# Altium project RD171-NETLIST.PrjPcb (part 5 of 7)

## Sheet 6.SchDoc
size 420 x 297 mm
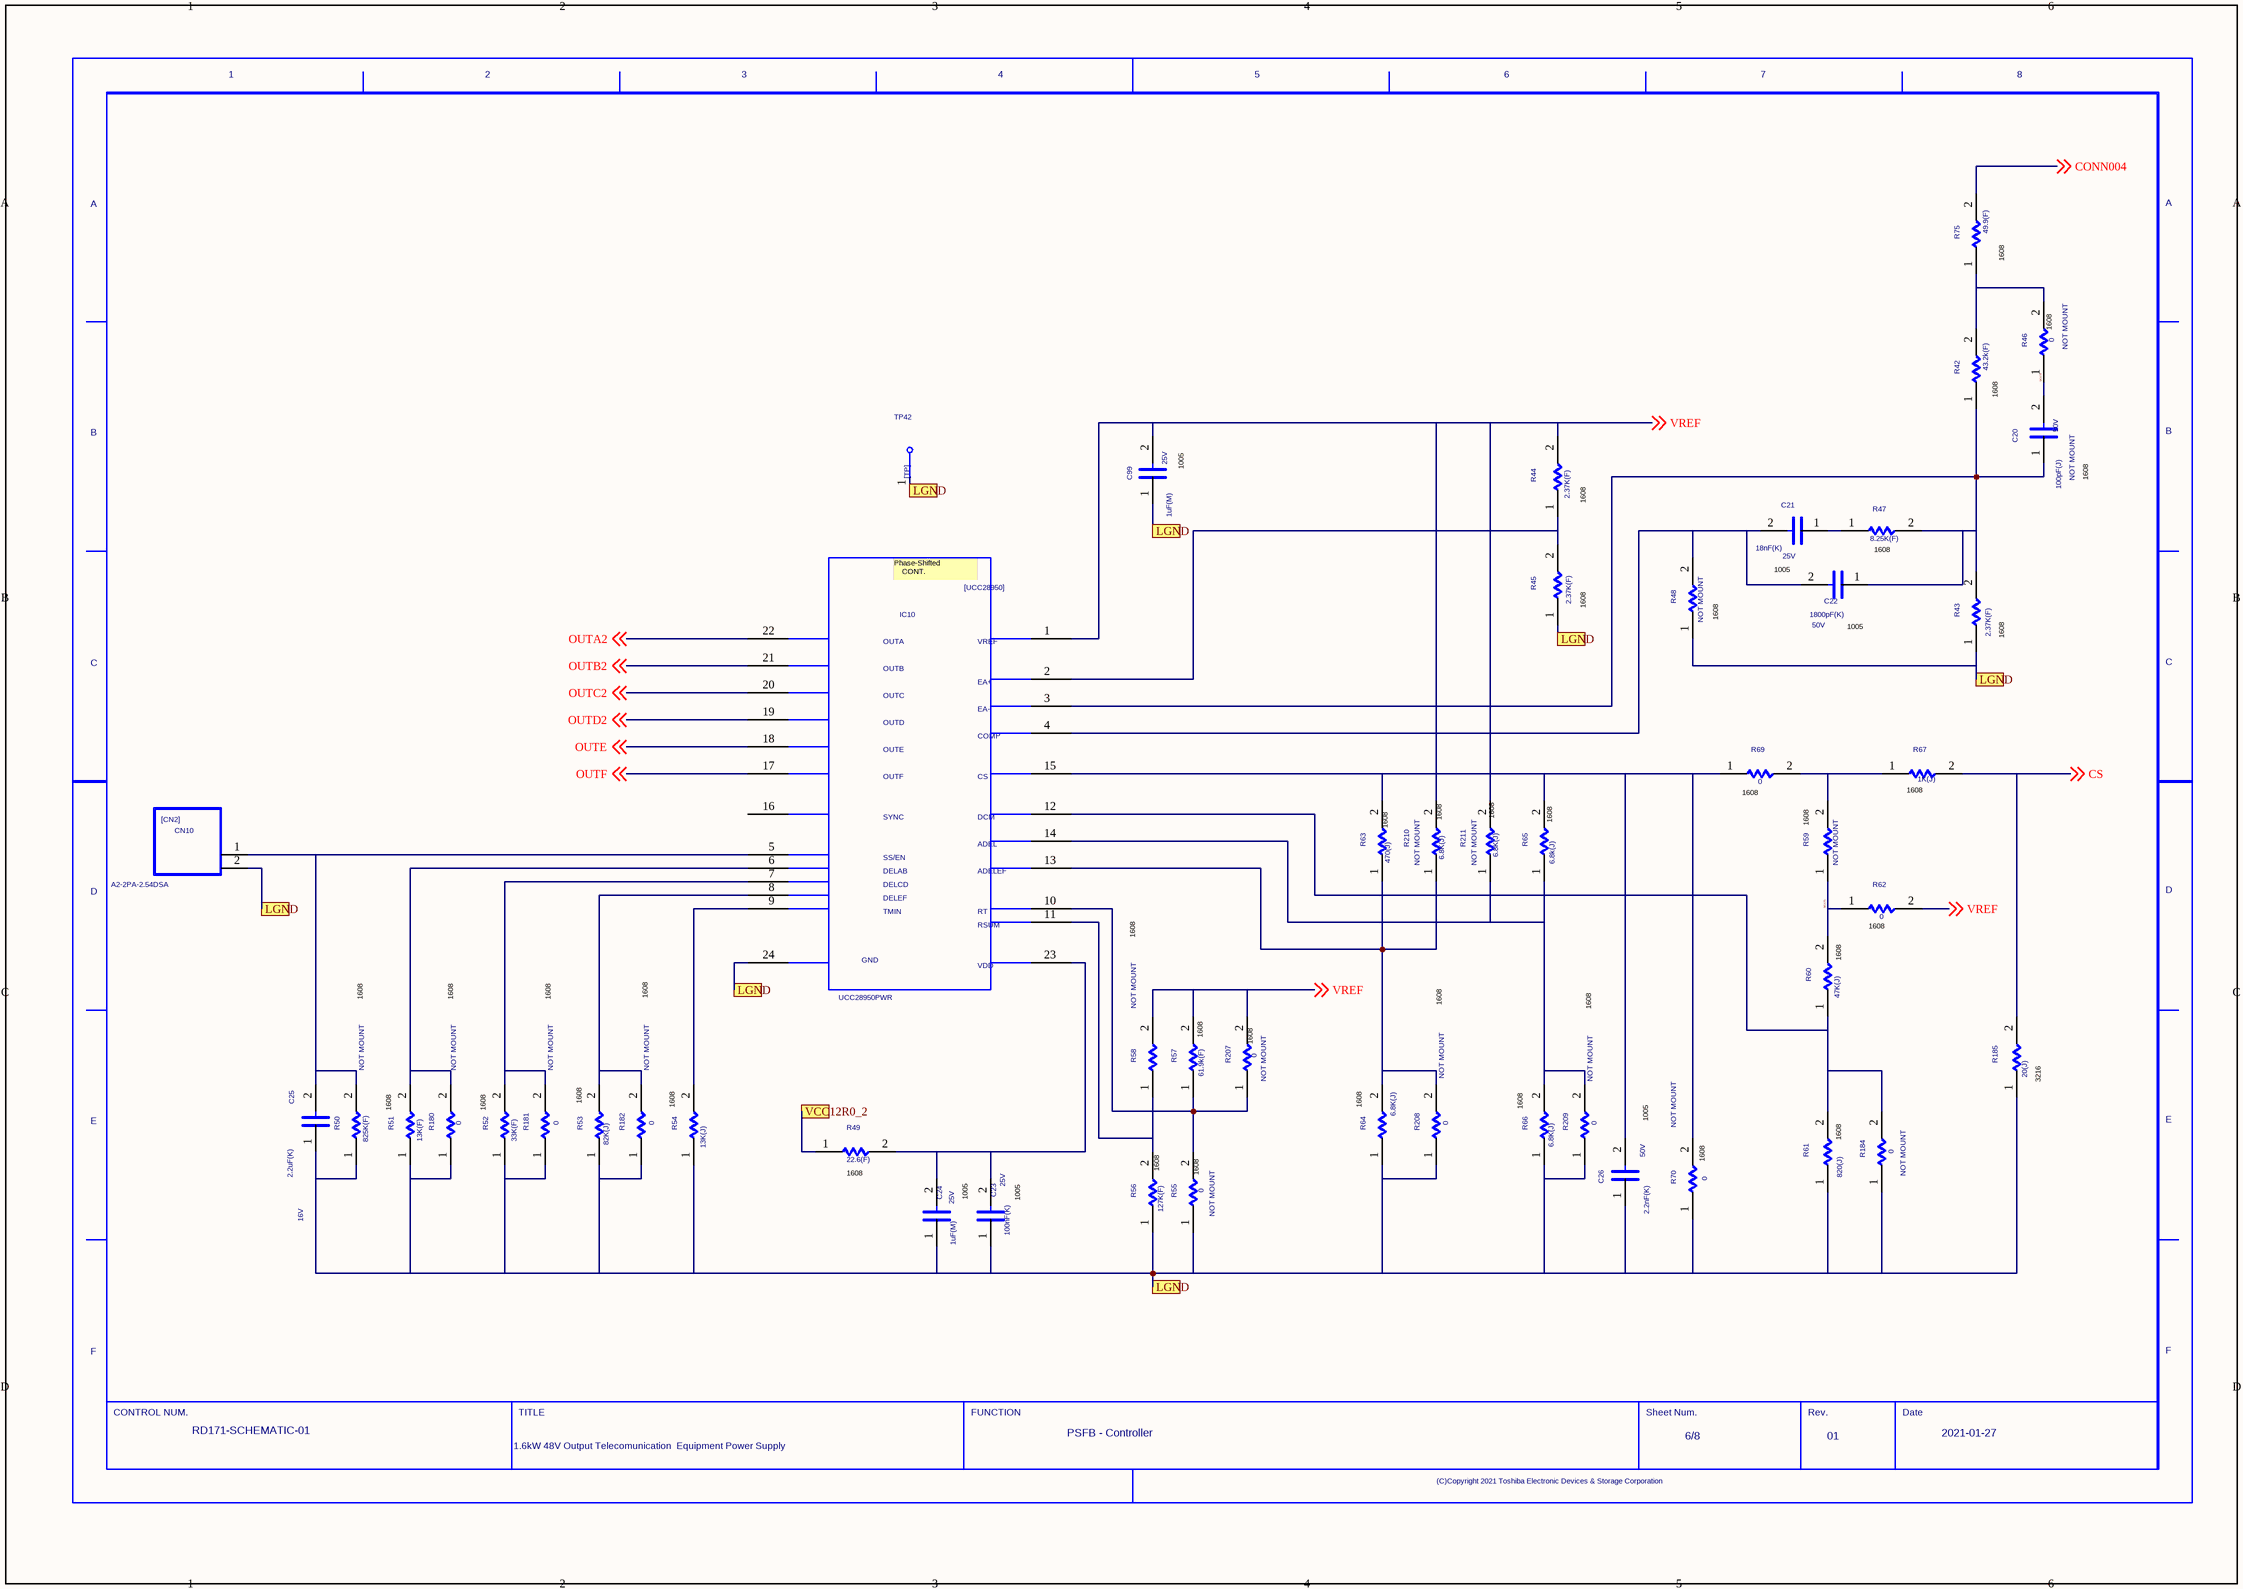
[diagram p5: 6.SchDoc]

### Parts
(Parts that share a designator on the sheet are numbered #1, #2 ... from top to bottom, then left to right.)
C20  VAL2: 50V  VAL1: 100pF(J)  NOTMOUNT: NOT MOUNT  (hidden comment: 100pF)
C21  VAL2: 25V  VAL1: 18nF(K)  (hidden comment: 18nF)
C22  VAL2: 50V  VAL1: 1800pF(K)  (hidden comment: 1800pF)
C23  VAL2: 25V  VAL1: 100nF(K)  (hidden comment: 100nF)
C24  VAL2: 25V  VAL1: 1uF(M)  (hidden comment: 1uF)
C25  VAL2: 16V  VAL1: 2.2uF(K)  (hidden comment: 2.2uF)
C26  VAL2: 50V  VAL1: 2.2nF(K)  (hidden comment: 2.2nF)
C99  VAL2: 25V  VAL1: 1uF(M)  (hidden comment: 1uF)
CN10  CN10  [A2-2PA-2.54DSA]  (value not drawn)
IC10  IC10  [UCC28950PWR]  (value not drawn)
R42  VAL1: 43.2k(F)  [RN73H1JTTD4322F25]  (hidden comment: 43.2k)
R43  VAL1: 2.37K(F)  (hidden comment: 2.37k)
R44  VAL1: 2.37K(F)  (hidden comment: 2.37k)
R45  VAL1: 2.37K(F)  (hidden comment: 2.37k)
R46  NOTMOUNT: NOT MOUNT  (hidden comment: 0)
R47  VAL1: 8.25K(F)  (hidden comment: 8.25k)
R48  NOTMOUNT: NOT MOUNT  (hidden comment: 0)
R49  VAL1: 22.6(F)  (hidden comment: 22.6)
R50  VAL1: 825K(F)  NOTMOUNT: NOT MOUNT  (hidden comment: 825k)
R51  VAL1: 13K(F)  (hidden comment: 13k)
R52  VAL1: 33K(F)  (hidden comment: 33k)
R53  VAL1: 82K(J)  (hidden comment: 100k)
R54  VAL1: 13K(J)  (hidden comment: 13k)
R55  NOTMOUNT: NOT MOUNT  (hidden comment: 0)
R56  VAL1: 127K(F)  (hidden comment: 127k)
R57  VAL1: 61.9k(F)  [RN73H1JTTD6192F50]  (hidden comment: 61.9k)
R58  NOTMOUNT: NOT MOUNT  (hidden comment: 0)
R59  NOTMOUNT: NOT MOUNT  (hidden comment: 0)
R60  VAL1: 47K(J)  (hidden comment: 47k)
R61  VAL1: 820(J)  (hidden comment: 820)
R62  0
R63  VAL1: 470(J)  (hidden comment: 100)
R64  VAL1: 6.8K(J)  (hidden comment: 6.8k)
R65  VAL1: 6.8k(J)  (hidden comment: 6.8k)
R66  VAL1: 6.8K(J)  (hidden comment: 6.8k)
R67  VAL1: 1K(J)  (hidden comment: 1K)
R69  0
R70  NOTMOUNT: NOT MOUNT  (hidden comment: 0)
R75  VAL1: 49.9(F)  (hidden comment: 49.9)
R180  NOTMOUNT: NOT MOUNT  (hidden comment: 0)
R181  NOTMOUNT: NOT MOUNT  (hidden comment: 0)
R182  NOTMOUNT: NOT MOUNT  (hidden comment: 0)
R184  NOTMOUNT: NOT MOUNT  (hidden comment: 0)
R185  VAL1: 20(J)  (hidden comment: 20)
R207  NOTMOUNT: NOT MOUNT  (hidden comment: 0)
R208  NOTMOUNT: NOT MOUNT  (hidden comment: 0)
R209  NOTMOUNT: NOT MOUNT  (hidden comment: 0)
R210  NOTMOUNT: NOT MOUNT  VAL1: 6.8K(J)  (hidden comment: 6.8k)
R211  NOTMOUNT: NOT MOUNT  VAL1: 6.8K(J)  (hidden comment: 6.8k)
TP42  TP42  [LC-22-S-BLACK]  (value not drawn)
U?#6  DATE: 2021-01-27  REVISION: 01  SHEETNUMBER: 6/8  FUNCTION: PSFB - Controller  TITLE: 1.6kW 48V Output Telecomunication / Equipment Power Supply  DRAWINGNUMBER: RD171-SCHEMATIC-01  (hidden comment: WAKU_DEF100)

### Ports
LGND, VCC12R0_2

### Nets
CONN004: R75.2 ; off-sheet CONN004
CS: R67.2 R185.2 ; off-sheet CS
LGND: C23.1 C24.1 C25.1 C26.1 C99.1 CN10.2 IC10.24 R43.1 R45.1 R48.1 R50.1 R51.1 R52.1 R53.1 R54.1 R55.1 R56.1 R61.1 R64.1 R66.1 R70.1 R180.1 R181.1 R182.1 R184.1 R185.1 R208.1 R209.1 TP42.1 ; port LGND
OUTA2: IC10.22 ; off-sheet OUTA2
OUTB2: IC10.21 ; off-sheet OUTB2
OUTC2: IC10.20 ; off-sheet OUTC2
OUTD2: IC10.19 ; off-sheet OUTD2
OUTE: IC10.18 ; off-sheet OUTE
OUTF: IC10.17 ; off-sheet OUTF
SIG148: IC10.6 R51.2 R180.2
SIG149: IC10.7 R52.2 R181.2
SIG150: IC10.8 R53.2 R182.2
SIG151: IC10.9 R54.2
SIG152: C25.2 CN10.1 IC10.5 R50.2
SIG154: IC10.2 R44.1 R45.2
SIG156: C20.1 C22.1 IC10.3 R42.1 R43.2 R47.2
SIG157: R42.2 R46.2 R75.1
SIG167: C21.1 R47.1
SIG168: C21.2 C22.2 IC10.4 R48.2
SIG170: C20.2 R46.1
SIG171: IC10.14 R65.1 R66.2 R209.2 R211.1
SIG172: IC10.13 R63.1 R64.2 R208.2 R210.1
SIG173: C26.2 IC10.15 R63.2 R65.2 R69.1 R70.2
SIG174: R59.2 R67.1 R69.2
SIG175: R59.1 R60.2 R62.1
SIG177: IC10.12 R60.1 R61.2 R184.2
SIG179: IC10.10 R55.2 R57.1 R207.1
SIG181: IC10.11 R56.2 R58.1
SIG183: C23.2 C24.2 IC10.23 R49.2
VREF: C99.2 IC10.1 R44.2 R57.2 R58.2 R62.2 R207.2 R210.2 R211.2 ; off-sheet VREF
NetC809_2: R49.1 ; port VCC12R0_2

Not connected (* = marked no-connect by the designer): IC10 16

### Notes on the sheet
- (near R75) 1608
- (near R46) 1608
- (near R42) 1608
- (near C99) 1005
- (near R44) 1608
- (near C20) 1608
- 1005
- (near R47) 1608
- (near R45) 1608
- (near R48) 1608
- (near C22) 1005
- (near R43) 1608
- (near R69) 1608
- (near R67) 1608
- (near R63) 1608
- (near R210) 1608
- (near R211) 1608
- (near R65) 1608
- (near R59) 1608
- 1608
- (near R62) 1608
- (near R60) 1608
- (near R57) 1608
- (near R207) 1608
- (near R51) 1608
- (near R52) 1608
- (near R53) 1608
- (near R64) 1608
- (near R66) 1608
- (near R61) 1608
- (near R185) 3216
- (near R49) 1608
- (near C23) 1005
- (near R56) 1608
- (near R55) 1608
- (near R70) 1608

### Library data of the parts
C20 = C: PARTNAME: Chip1608_GS_1; ORIGINALSYMBOLORIGIN: (0,0); TIME: 16:40:04; UPDATEUSER: t5459927; SAVECOUNT: 1; QUADMODEL: CON_100N; FUNCTION: C_C.Normal_package; NOMINALCAPACITA: 100n; RATEDVOLTAGE: 25; CDMASTERCADCELG: KC0008; TEMPCHARACTERI2: B; SIZECODESMD: 1608; OUMEMAKER: MRT 村田製作所; COMP: PRT_48; ADSMODELNAME: s_GRM188B11E104KA01D; PMPRODUCTSTYPEG: PC1; FNLEADFREETHET1GT2GMCTH1: 3_1_N; VAL3: GRM1885C1H101JA01D; CAPACITANCETOLE: K; OUMECLASSIFICATION: セラミックコンデンサ; OUMEMAKERKATAMEI: GRM188B11E104KA01D; INSTANCENAME: INS8954
C21 = C: PARTNAME: Chip1005_GS_2; ORIGINALSYMBOLORIGIN: (0,0); TIME: 16:40:04; UPDATEUSER: t5459927; SAVECOUNT: 1; QUADMODEL: CON_5.6N; FUNCTION: C_C.Normal_package; NOMINALCAPACITA: 5.6n; RATEDVOLTAGE: 25; CDMASTERCADCELG: KC0005; MAKER: MURATA; TEMPCHARACTERI2: B; SIZECODESMD: 1005; OUMEMAKER: MRT 村田製作所; ADSCNVFLAG: ON; ADSCOMPONENTNAME: C_1005; COMP: PRT_52; ADSMODELNAME: s_GRM155B11E562KA01D; PMPRODUCTSTYPEG: HD1; FNLEADFREETHET1GT2GMCTH1: 2_0_N; VAL3: GRM155R71E183KA61D; CAPACITANCETOLE: K; OUMECLASSIFICATION: セラミックコンデンサ; OUMEMAKERKATAMEI: GRM155B11E562KA01D; INSTANCENAME: INS8656
C22 = C: PARTNAME: Chip1005_GS_2; ORIGINALSYMBOLORIGIN: (0,0); TIME: 16:40:04; UPDATEUSER: t5459927; SAVECOUNT: 1; QUADMODEL: CON_560P; FUNCTION: C_C.Normal_package; NOMINALCAPACITA: 560p; RATEDVOLTAGE: 50; CDMASTERCADCELG: KC0005; MAKER: MURATA; TEMPCHARACTERI2: B; SIZECODESMD: 1005; OUMEMAKER: TDK ＴＤＫ; ADSCNVFLAG: ON; ADSCOMPONENTNAME: C_1005; COMP: PRT_52; ADSMODELNAME: s_C1005JB1H561KT; PMPRODUCTSTYPEG: HD1-PC1; FNLEADFREETHET1GT2GMCTH1: 2_0_N; VAL3: GRM155R71H182KA01D; CAPACITANCETOLE: K; OUMECLASSIFICATION: セラミックコンデンサ; OUMEMAKERKATAMEI: C1005JB1H561KT; INSTANCENAME: INS8666
C23 = C: PARTNAME: Chip1005_GS_2; ORIGINALSYMBOLORIGIN: (0,0); TIME: 16:40:04; UPDATEUSER: t5459927; SAVECOUNT: 1; QUADMODEL: CON_100N; FUNCTION: C_C.Normal_package; NOMINALCAPACITA: 100n; RATEDVOLTAGE: 25; CDMASTERCADCELG: KC0005; MAKER: TDK; SIZECODESMD: 1005; OUMEMAKER: MRT 村田製作所; COMP: PRT_52; ADSMODELNAME: s_GRM155R71E104KE14D; FNLEADFREETHET1GT2GMCTH1: N_N_N; VAL3: C1005X7R1E104K050BB; CAPACITANCETOLE: K; OUMECLASSIFICATION: セラミックコンデンサ; OUMEMAKERKATAMEI: GRM155R71E104KE14D; INSTANCENAME: INS8708
C24 = C: PARTNAME: Chip1005_GS_2; ORIGINALSYMBOLORIGIN: (0,0); TIME: 16:40:04; UPDATEUSER: t5459927; SAVECOUNT: 1; QUADMODEL: CON_1U; FUNCTION: C_C.Normal_package; NOMINALCAPACITA: 1u; RATEDVOLTAGE: 25; CDMASTERCADCELG: KC0005; MAKER: TDK; TEMPCHARACTERI2: B; SIZECODESMD: 1005; OUMEMAKER: MRT 村田製作所; COMP: PRT_52; ADSMODELNAME: s_GRM155B31E105KA12D; PMPRODUCTSTYPEG: HD1; FNLEADFREETHET1GT2GMCTH1: 3_0_N; VAL3: C1005X5R1E105M050BC; CAPACITANCETOLE: K; OUMECLASSIFICATION: セラミックコンデンサ; OUMEMAKERKATAMEI: GRM155B31E105KA12D; INSTANCENAME: INS8718
C25 = C: PARTNAME: Chip1005_GS_2; ORIGINALSYMBOLORIGIN: (0,0); TIME: 16:40:04; UPDATEUSER: t5459927; SAVECOUNT: 1; FUNCTION: C_C.Normal_package; NOMINALCAPACITA: 150n; RATEDVOLTAGE: 25; CDMASTERCADCELG: KC0005; MAKER: MURATA; SIZECODESMD: 1005; COMP: PRT_52; ADSMODELNAME: s_GRM155C81C225KE11; PMPRODUCTSTYPEG: HD1; FNLEADFREETHET1GT2GMCTH1: 3_0_N; VAL3: GRM155C81C225KE11; CAPACITANCETOLE: K; OUMECLASSIFICATION: セラミックコンデンサ; INSTANCENAME: INS8624
C26 = C: PARTNAME: Chip1005_GS_2; ORIGINALSYMBOLORIGIN: (0,0); TIME: 16:40:04; UPDATEUSER: t5459927; SAVECOUNT: 1; QUADMODEL: CON_2.2N; FUNCTION: C_C.Normal_package; NOMINALCAPACITA: 2.2n; RATEDVOLTAGE: 50; CDMASTERCADCELG: KC0005; MAKER: TDK; TEMPCHARACTERI2: B; SIZECODESMD: 1005; OUMEMAKER: TYD 太陽誘電; COMP: PRT_52; ADSMODELNAME: s_UMK105BJ222KV_F; PMPRODUCTSTYPEG: HD1-PC1; FNLEADFREETHET1GT2GMCTH1: 2_0_N; VAL3: UMK105BJ222KV-F; CAPACITANCETOLE: K; OUMECLASSIFICATION: セラミックコンデンサ; INSTANCENAME: INS8762
C99 = C: PARTNAME: Chip1005_GS_2; ORIGINALSYMBOLORIGIN: (0,0); TIME: 16:40:04; UPDATEUSER: t5459927; SAVECOUNT: 1; QUADMODEL: CON_1U; FUNCTION: C_C.Normal_package; NOMINALCAPACITA: 1u; RATEDVOLTAGE: 25; CDMASTERCADCELG: KC0005; MAKER: TDK; TEMPCHARACTERI2: B; SIZECODESMD: 1005; OUMEMAKER: MRT 村田製作所; COMP: PRT_52; ADSMODELNAME: s_GRM155B31E105KA12D; PMPRODUCTSTYPEG: HD1; FNLEADFREETHET1GT2GMCTH1: 3_0_N; VAL3: C1005X5R1E105M050BC; CAPACITANCETOLE: K; OUMECLASSIFICATION: セラミックコンデンサ; OUMEMAKERKATAMEI: GRM155B31E105KA12D; INSTANCENAME: INS8728
CN10 = CN2: PARTNAME: A2-2PA-2.54DSA_HR; ORIGINALSYMBOLORIGIN: (0,0); TIME: 16:40:05; UPDATEUSER: t5459927; SAVECOUNT: 1; COMP: PRT_56; FUNCTION: CN2_CN2.Normal_package; MAKER: HIROSE; INSTANCENAME: INS9156
IC10 = L28950: PARTNAME: UCC28950PWR_GS_1; UPDATEUSER: t5459927; UPDATETIME: 16:40:04; SAVECOUNT: 1; SAVEAREA0: -41645,-82886,84834,-24583; ORIGINALSYMBOLORIGIN: (0,0); COMP: PRT_16; FUNCTION: L28950_L28950.Normal_package; MAKER: TEXAS; INSTANCENAME: INS8570
R42 = R: PARTNAME: Chip1608_GS_1; ORIGINALSYMBOLORIGIN: (0,0); TIME: 16:40:04; UPDATEUSER: t5459927; SAVECOUNT: 1; QUADMODEL: RES_9.09K; FUNCTION: R_R.Normal_package; CDMASTERCADCELG: KC0008; MAKER: PANASONIC; RESISTANCETOLER: B; SIZECODESMD: 1608; OUMEMAKER: KOA コーア; POWERRATING: 100m; MOUNTINGFORMSMD: SMD; NOMINALRESISTAN: 9.09K; COMP: PRT_8; ADSMODELNAME: s_RN73H1JTTD4322F25; PMPRODUCTSTYPEG: DME; FNLEADFREETHET1GT2GMCTH1: N_N_N; VAL3: ERJ-3EKF9091V; VAL2: 100mW,±1%; OUMECLASSIFICATION: 表面実装用固定抵抗器; OUMEMAKERKATAMEI: RN73H1JTTD9091B10; INSTANCENAME: INS8646
R43 = R: PARTNAME: Chip1608_GS_1; ORIGINALSYMBOLORIGIN: (0,0); TIME: 16:40:04; UPDATEUSER: t5459927; SAVECOUNT: 1; QUADMODEL: RES_2.2K; FUNCTION: R_R.Normal_package; CDMASTERCADCELG: KC0165; MAKER: PANASONIC; RESISTANCETOLER: F; SIZECODESMD: 1608; OUMEMAKER: NAE パナソニックエレクトロニックデバイス; POWERRATING: 100m; MOUNTINGFORMSMD: SMD; NOMINALRESISTAN: 2.2K; COMP: PRT_8; ADSMODELNAME: s_ERJ3EKF2201V@@; PMPRODUCTSTYPEG: DA; FNLEADFREETHET1GT2GMCTH1: 3_2_N; VAL3: ERJ-3EKF2371V; VAL2: 100mW,±1%; OUMECLASSIFICATION: 表面実装用固定抵抗器; OUMEMAKERKATAMEI: ERJ3EKF2201V@@; INSTANCENAME: INS8966
R44 = R: PARTNAME: Chip1608_GS_1; ORIGINALSYMBOLORIGIN: (0,0); TIME: 16:40:04; UPDATEUSER: t5459927; SAVECOUNT: 1; QUADMODEL: RES_2.2K; FUNCTION: R_R.Normal_package; CDMASTERCADCELG: KC0165; MAKER: PANASONIC; RESISTANCETOLER: F; SIZECODESMD: 1608; OUMEMAKER: NAE パナソニックエレクトロニックデバイス; POWERRATING: 100m; MOUNTINGFORMSMD: SMD; NOMINALRESISTAN: 2.2K; COMP: PRT_8; ADSMODELNAME: s_ERJ3EKF2201V@@; PMPRODUCTSTYPEG: DA; FNLEADFREETHET1GT2GMCTH1: 3_2_N; VAL3: ERJ-3EKF2371V; VAL2: 100mW,±1%; OUMECLASSIFICATION: 表面実装用固定抵抗器; OUMEMAKERKATAMEI: ERJ3EKF2201V@@; INSTANCENAME: INS8878
R45 = R: PARTNAME: Chip1608_GS_1; ORIGINALSYMBOLORIGIN: (0,0); TIME: 16:40:04; UPDATEUSER: t5459927; SAVECOUNT: 1; QUADMODEL: RES_2.2K; FUNCTION: R_R.Normal_package; CDMASTERCADCELG: KC0165; MAKER: PANASONIC; RESISTANCETOLER: F; SIZECODESMD: 1608; OUMEMAKER: NAE パナソニックエレクトロニックデバイス; POWERRATING: 100m; MOUNTINGFORMSMD: SMD; NOMINALRESISTAN: 2.2K; COMP: PRT_8; ADSMODELNAME: s_ERJ3EKF2201V@@; PMPRODUCTSTYPEG: DA; FNLEADFREETHET1GT2GMCTH1: 3_2_N; VAL3: ERJ-3EKF2371V; VAL2: 100mW,±1%; OUMECLASSIFICATION: 表面実装用固定抵抗器; OUMEMAKERKATAMEI: ERJ3EKF2201V@@; INSTANCENAME: INS8868
R46 = R: PARTNAME: Chip1608_GS_1; ORIGINALSYMBOLORIGIN: (0,0); TIME: 16:40:04; UPDATEUSER: t5459927; SAVECOUNT: 1; QUADMODEL: RES_9.09K; FUNCTION: R_R.Normal_package; CDMASTERCADCELG: KC0008; MAKER: KOA; RESISTANCETOLER: B; SIZECODESMD: 1608; OUMEMAKER: KOA コーア; POWERRATING: 100m; MOUNTINGFORMSMD: SMD; NOMINALRESISTAN: 9.09K; COMP: PRT_8; ADSMODELNAME: s_RN73H1JTTD9091B10; PMPRODUCTSTYPEG: DME; FNLEADFREETHET1GT2GMCTH1: N_N_N; VAL3: RK73Z1JTTD; VAL2: 100mW; OUMECLASSIFICATION: 表面実装用固定抵抗器; OUMEMAKERKATAMEI: RN73H1JTTD9091B10; INSTANCENAME: INS8676
R47 = R: PARTNAME: Chip1608_GS_1; ORIGINALSYMBOLORIGIN: (0,0); TIME: 16:40:04; UPDATEUSER: t5459927; SAVECOUNT: 1; QUADMODEL: RES_8.25K; FUNCTION: R_R.Normal_package; CDMASTERCADCELG: KC0167; MAKER: PANASONIC; RESISTANCETOLER: F; SIZECODESMD: 1608; OUMEMAKER: NAE パナソニックエレクトロニックデバイス; POWERRATING: 100m; MOUNTINGFORMSMD: SMD; COMP: PRT_8; ADSMODELNAME: s_ERJ3EKF8251V; FNLEADFREETHET1GT2GMCTH1: N_N_N; VAL3: ERJ-3EKF8251V; VAL2: 100mW,±1%; OUMECLASSIFICATION: 表面実装用固定抵抗器; OUMEMAKERKATAMEI: ERJ3EKF8251V; INSTANCENAME: INS8996
R48 = R: PARTNAME: Chip1608_GS_1; ORIGINALSYMBOLORIGIN: (0,0); TIME: 16:40:04; UPDATEUSER: t5459927; SAVECOUNT: 1; QUADMODEL: RES_0; FUNCTION: R_R.Normal_package; CDMASTERCADCELG: KCK0203; MAKER: KOA; RESISTANCETOLER: X; SIZECODESMD: 1608; OUMEMAKER: KOA コーア; POWERRATING: 100m; MOUNTINGFORMSMD: SMD; COMP: PRT_8; ADSMODELNAME: s_RK73Z1JTTD; PMPRODUCTSTYPEG: DME-HD1-PC1; FNLEADFREETHET1GT2GMCTH1: 3_2_N; VAL3: RK73Z1JTTD; VAL2: 100mW; OUMECLASSIFICATION: 表面実装用固定抵抗器; INSTANCENAME: INS8976
R49 = R: PARTNAME: Chip1608_GS_1; ORIGINALSYMBOLORIGIN: (0,0); TIME: 16:40:04; UPDATEUSER: t5459927; SAVECOUNT: 1; QUADMODEL: RES_22; FUNCTION: R_R.Normal_package; CDMASTERCADCELG: KC0008; MAKER: PANASONIC; RESISTANCETOLER: J; SIZECODESMD: 1608; OUMEMAKER: KOA コーア; POWERRATING: 100m; MOUNTINGFORMSMD: SMD; NOMINALRESISTAN: 22; COMP: PRT_8; ADSMODELNAME: s_RK73B1JRTTD220J; FNLEADFREETHET1GT2GMCTH1: N_N_N; VAL3: ERJ-3EKF22R6V; VAL2: 100mW,±1%; OUMECLASSIFICATION: 表面実装用固定抵抗器; OUMEMAKERKATAMEI: RK73B1JRTTD220J; INSTANCENAME: INS8858
R50 = R: PARTNAME: Chip1608_GS_1; ORIGINALSYMBOLORIGIN: (0,0); TIME: 16:40:04; UPDATEUSER: t5459927; SAVECOUNT: 1; QUADMODEL: RES_825K; FUNCTION: R_R.Normal_package; CDMASTERCADCELG: DR802R; MAKER: PANASONIC; RESISTANCETOLER: F; SIZECODESMD: 1608; OUMEMAKER: ROH ロー・; ADSCNVFLAG: ON; POWERRATING: 100m; MOUNTINGFORMSMD: SMD; ADSCOMPONENTNAME: R_1608; COMP: PRT_8; ADSMODELNAME: s_MCR03EZHF8253; FNLEADFREETHET1GT2GMCTH1: 3_1_N; VAL3: ERJ-3EKF8253V; VAL2: 100mW,±1%; OUMECLASSIFICATION: 表面実装用固定抵抗器; OUMEMAKERKATAMEI: MCR03EZHF8253; INSTANCENAME: INS8634
R51 = R: PARTNAME: Chip1608_GS_1; ORIGINALSYMBOLORIGIN: (0,0); TIME: 16:40:04; UPDATEUSER: t5459927; SAVECOUNT: 1; QUADMODEL: RES_13K; FUNCTION: R_R.Normal_package; CDMASTERCADCELG: KC0008; MAKER: PANASONIC; RESISTANCETOLER: B; SIZECODESMD: 1608; OUMEMAKER: KOA コーア; POWERRATING: 100m; MOUNTINGFORMSMD: SMD; COMP: PRT_8; ADSMODELNAME: s_RN73H1JTTD1302B10; FNLEADFREETHET1GT2GMCTH1: N_N_N; VAL3: RK73H1JTTD1302F; VAL2: 100mW,±1%; OUMECLASSIFICATION: 表面実装用固定抵抗器; OUMEMAKERKATAMEI: RN73H1JTTD1302B10; INSTANCENAME: INS8782
R52 = R: PARTNAME: Chip1608_GS_1; ORIGINALSYMBOLORIGIN: (0,0); TIME: 16:40:04; UPDATEUSER: t5459927; SAVECOUNT: 1; QUADMODEL: RES_33K; FUNCTION: R_R.Normal_package; CDMASTERCADCELG: KC0008; MAKER: PANASONIC; RESISTANCETOLER: B; SIZECODESMD: 1608; OUMEMAKER: KOA コーア; POWERRATING: 100m; MOUNTINGFORMSMD: SMD; COMP: PRT_8; ADSMODELNAME: s_RN73H1JTTD3302B10; FNLEADFREETHET1GT2GMCTH1: N_N_N; VAL3: RK73H1JTTD3302F; VAL2: 100mW,±1%; OUMECLASSIFICATION: 表面実装用固定抵抗器; OUMEMAKERKATAMEI: RN73H1JTTD2202B10; INSTANCENAME: INS8792
R53 = R: PARTNAME: Chip1608_GS_1; ORIGINALSYMBOLORIGIN: (0,0); TIME: 16:40:04; UPDATEUSER: t5459927; SAVECOUNT: 1; QUADMODEL: RES_100K; FUNCTION: R_R.Normal_package; CDMASTERCADCELG: KC0008; MAKER: KOA; RESISTANCETOLER: G; SIZECODESMD: 1608; OUMEMAKER: KOA コーア; POWERRATING: 100m; MOUNTINGFORMSMD: SMD; COMP: PRT_8; ADSMODELNAME: s_RK73B1JTTD104G; FNLEADFREETHET1GT2GMCTH1: N_N_N; VAL3: RK73B1JTTD104J; VAL2: 100mW,±5%; OUMECLASSIFICATION: 表面実装用固定抵抗器; OUMEMAKERKATAMEI: RK73B1JTTD104G; INSTANCENAME: INS8838
R54 = R: PARTNAME: Chip1608_GS_1; ORIGINALSYMBOLORIGIN: (0,0); TIME: 16:40:04; UPDATEUSER: t5459927; SAVECOUNT: 1; QUADMODEL: RES_15K; FUNCTION: R_R.Normal_package; CDMASTERCADCELG: KCK0203; MAKER: KOA; RESISTANCETOLER: F; SIZECODESMD: 1608; OUMEMAKER: KOA コーア; ADSCNVFLAG: ON; POWERRATING: 100m; MOUNTINGFORMSMD: SMD; ADSCOMPONENTNAME: R_1608; NOMINALRESISTAN: 15K; COMP: PRT_8; ADSMODELNAME: s_RK73H1JTTD1502F; PMPRODUCTSTYPEG: DME; FNLEADFREETHET1GT2GMCTH1: 3_2_N; VAL3: RK73B1JTTD153J; VAL2: 100mW,±5%; OUMECLASSIFICATION: 表面実装用固定抵抗器; OUMEMAKERKATAMEI: RK73H1JTTD1502F; INSTANCENAME: INS8848
R55 = R: PARTNAME: Chip1608_GS_1; ORIGINALSYMBOLORIGIN: (0,0); TIME: 16:40:04; UPDATEUSER: t5459927; SAVECOUNT: 1; QUADMODEL: RES_0; FUNCTION: R_R.Normal_package; CDMASTERCADCELG: KCK0203; MAKER: KOA; RESISTANCETOLER: X; SIZECODESMD: 1608; OUMEMAKER: KOA コーア; POWERRATING: 100m; MOUNTINGFORMSMD: SMD; COMP: PRT_8; ADSMODELNAME: s_RK73Z1JTTD; PMPRODUCTSTYPEG: DME-HD1-PC1; FNLEADFREETHET1GT2GMCTH1: 3_2_N; VAL3: RK73Z1JTTD; VAL2: 100mW; OUMECLASSIFICATION: 表面実装用固定抵抗器; INSTANCENAME: INS9098
R56 = R: PARTNAME: Chip1608_GS_1; ORIGINALSYMBOLORIGIN: (0,0); TIME: 16:40:04; UPDATEUSER: t5459927; SAVECOUNT: 1; QUADMODEL: RES_120K; FUNCTION: R_R.Normal_package; CDMASTERCADCELG: KC0008; MAKER: PANASONIC; RESISTANCETOLER: F; SIZECODESMD: 1608; OUMEMAKER: NAE パナソニックエレクトロニックデバイス; POWERRATING: 100m; MOUNTINGFORMSMD: SMD; NOMINALRESISTAN: 120K; COMP: PRT_8; ADSMODELNAME: s_ERJ3EKF1203V; FNLEADFREETHET1GT2GMCTH1: N_N_N; VAL3: ERJ-3EKF1273V; VAL2: 100mW,±1%; OUMECLASSIFICATION: 表面実装用固定抵抗器; OUMEMAKERKATAMEI: ERJ3EKF1203V; INSTANCENAME: INS9088
R57 = R: PARTNAME: Chip1608_GS_1; ORIGINALSYMBOLORIGIN: (0,0); TIME: 16:40:04; UPDATEUSER: t5459927; SAVECOUNT: 1; QUADMODEL: RES_100K; FUNCTION: R_R.Normal_package; CDMASTERCADCELG: DR802R; MAKER: PANASONIC; RESISTANCETOLER: J; SIZECODESMD: 1608; OUMEMAKER: NAE パナソニックエレクトロニックデバイス; POWERRATING: 63m; MOUNTINGFORMSMD: SMD; NOMINALRESISTAN: 100K; COMP: PRT_8; ADSMODELNAME: s_ERJ3GEYJ104V; FNLEADFREETHET1GT2GMCTH1: 3_1_N; VAL3: ERJ-3EKF1003V; VAL2: 100mW,±1%; OUMECLASSIFICATION: 表面実装用固定抵抗器; OUMEMAKERKATAMEI: ERJ3GEYJ104V; INSTANCENAME: INS8772
R58 = R: PARTNAME: Chip1608_GS_1; ORIGINALSYMBOLORIGIN: (0,0); TIME: 16:40:04; UPDATEUSER: t5459927; SAVECOUNT: 1; QUADMODEL: RES_0; FUNCTION: R_R.Normal_package; CDMASTERCADCELG: KCK0203; MAKER: KOA; RESISTANCETOLER: X; SIZECODESMD: 1608; OUMEMAKER: KOA コーア; POWERRATING: 100m; MOUNTINGFORMSMD: SMD; COMP: PRT_8; ADSMODELNAME: s_RK73Z1JTTD; PMPRODUCTSTYPEG: DME-HD1-PC1; FNLEADFREETHET1GT2GMCTH1: 3_2_N; VAL3: RK73Z1JTTD; VAL2: 100mW; OUMECLASSIFICATION: 表面実装用固定抵抗器; INSTANCENAME: INS9078
R59 = R: PARTNAME: Chip1608_GS_1; ORIGINALSYMBOLORIGIN: (0,0); TIME: 16:40:04; UPDATEUSER: t5459927; SAVECOUNT: 1; QUADMODEL: RES_0; FUNCTION: R_R.Normal_package; CDMASTERCADCELG: KCK0203; MAKER: KOA; RESISTANCETOLER: X; SIZECODESMD: 1608; OUMEMAKER: KOA コーア; POWERRATING: 100m; MOUNTINGFORMSMD: SMD; COMP: PRT_8; ADSMODELNAME: s_RK73Z1JTTD; PMPRODUCTSTYPEG: DME-HD1-PC1; FNLEADFREETHET1GT2GMCTH1: 3_2_N; VAL3: RK73Z1JTTD; VAL2: 100mW; OUMECLASSIFICATION: 表面実装用固定抵抗器; INSTANCENAME: INS9006
R60 = R: PARTNAME: Chip1608_GS_1; ORIGINALSYMBOLORIGIN: (0,0); TIME: 16:40:04; UPDATEUSER: t5459927; SAVECOUNT: 1; QUADMODEL: RES_47K; FUNCTION: R_R.Normal_package; CDMASTERCADCELG: KC0008; MAKER: KOA; RESISTANCETOLER: G; SIZECODESMD: 1608; OUMEMAKER: KOA コーア; POWERRATING: 100m; MOUNTINGFORMSMD: SMD; COMP: PRT_8; ADSMODELNAME: s_RK73B1JTTD473G; FNLEADFREETHET1GT2GMCTH1: N_N_N; VAL3: RK73B1JTTD473J; VAL2: 100mW,±5%; OUMECLASSIFICATION: 表面実装用固定抵抗器; OUMEMAKERKATAMEI: RK73B1JTTD473G; INSTANCENAME: INS9036
R61 = R: PARTNAME: Chip1608_GS_1; ORIGINALSYMBOLORIGIN: (0,0); TIME: 16:40:04; UPDATEUSER: t5459927; SAVECOUNT: 1; QUADMODEL: RES_820; FUNCTION: R_R.Normal_package; CDMASTERCADCELG: DR802R; MAKER: KOA; RESISTANCETOLER: D; SIZECODESMD: 1608; OUMEMAKER: KOA コーア; POWERRATING: 63m; MOUNTINGFORMSMD: SMD; COMP: PRT_8; ADSMODELNAME: s_RK73G1JTD821D; FNLEADFREETHET1GT2GMCTH1: 3_1_N; VAL3: RK73B1JTTD821J; VAL2: 125mW,±5%; OUMECLASSIFICATION: 表面実装用固定抵抗器; OUMEMAKERKATAMEI: RK73G1JTD821D; INSTANCENAME: INS9046
R62 = R: PARTNAME: Chip1608_GS_1; ORIGINALSYMBOLORIGIN: (0,0); TIME: 16:40:04; UPDATEUSER: t5459927; SAVECOUNT: 1; QUADMODEL: RES_0; FUNCTION: R_R.Normal_package; CDMASTERCADCELG: KCK0203; MAKER: KOA; RESISTANCETOLER: X; SIZECODESMD: 1608; OUMEMAKER: KOA コーア; POWERRATING: 100m; MOUNTINGFORMSMD: SMD; COMP: PRT_8; ADSMODELNAME: s_RK73Z1JTTD; PMPRODUCTSTYPEG: DME-HD1-PC1; FNLEADFREETHET1GT2GMCTH1: 3_2_N; VAL3: RK73Z1JTTD; VAL2: 100mW; OUMECLASSIFICATION: 表面実装用固定抵抗器; INSTANCENAME: INS9016
R63 = R: PARTNAME: Chip1608_GS_1; ORIGINALSYMBOLORIGIN: (0,0); TIME: 16:40:04; UPDATEUSER: t5459927; SAVECOUNT: 1; COMP: PRT_8; CHIPSIZE: 1608; ADSCOMPONENTNAME: R_1005; FUNCTION: R_R.Normal_package; ADSMODELNAME: s_CR10_000V; MOUNTINGFORMSMD: SMD; VAL3: RK73B1JTTD101J; VAL2: 125mW,±5%; MAKER: KOA; INSTANCENAME: INS8688
R64 = R: PARTNAME: Chip1608_GS_1; ORIGINALSYMBOLORIGIN: (0,0); TIME: 16:40:04; UPDATEUSER: t5459927; SAVECOUNT: 1; QUADMODEL: RES_6.8K; FUNCTION: R_R.Normal_package; CDMASTERCADCELG: KCK0203; MAKER: KOA; RESISTANCETOLER: B; SIZECODESMD: 1608; OUMEMAKER: KOA コーア; POWERRATING: 100m; MOUNTINGFORMSMD: SMD; COMP: PRT_8; ADSMODELNAME: s_RN73H1JTTD6801B10; PMPRODUCTSTYPEG: DME; FNLEADFREETHET1GT2GMCTH1: N_N_N; VAL3: RK73B1JTTD682J; VAL2: 100mW,±5%; OUMECLASSIFICATION: 表面実装用固定抵抗器; OUMEMAKERKATAMEI: RN73H1JTTD6801B10; INSTANCENAME: INS8888
R65 = R: PARTNAME: Chip1608_GS_1; ORIGINALSYMBOLORIGIN: (0,0); TIME: 16:40:04; UPDATEUSER: t5459927; SAVECOUNT: 1; COMP: PRT_8; CHIPSIZE: 1608; ADSCOMPONENTNAME: R_1005; FUNCTION: R_R.Normal_package; ADSMODELNAME: s_CR10_000V; MOUNTINGFORMSMD: SMD; VAL3: RK73B1JTTD682J; VAL2: 100mW,±5%; MAKER: KOA; INSTANCENAME: INS8698
R66 = R: PARTNAME: Chip1608_GS_1; ORIGINALSYMBOLORIGIN: (0,0); TIME: 16:40:04; UPDATEUSER: t5459927; SAVECOUNT: 1; QUADMODEL: RES_6.8K; FUNCTION: R_R.Normal_package; CDMASTERCADCELG: KCK0203; MAKER: KOA; RESISTANCETOLER: B; SIZECODESMD: 1608; OUMEMAKER: KOA コーア; POWERRATING: 100m; MOUNTINGFORMSMD: SMD; COMP: PRT_8; ADSMODELNAME: s_RN73H1JTTD6801B10; PMPRODUCTSTYPEG: DME; FNLEADFREETHET1GT2GMCTH1: N_N_N; VAL3: RK73B1JTTD682J; VAL2: 100mW,±5%; OUMECLASSIFICATION: 表面実装用固定抵抗器; OUMEMAKERKATAMEI: RN73H1JTTD6801B10; INSTANCENAME: INS8898
R67 = R: PARTNAME: Chip1608_GS_1; ORIGINALSYMBOLORIGIN: (0,0); TIME: 16:40:04; UPDATEUSER: t5459927; SAVECOUNT: 1; QUADMODEL: RES_1K; FUNCTION: R_R.Normal_package; CDMASTERCADCELG: KC0008; MAKER: KOA; RESISTANCETOLER: B; SIZECODESMD: 1608; OUMEMAKER: KOA コーア; POWERRATING: 100m; MOUNTINGFORMSMD: SMD; COMP: PRT_8; ADSMODELNAME: s_RN73H1JTTD1001B10; FNLEADFREETHET1GT2GMCTH1: N_N_N; VAL3: RK73B1JTTD102J; VAL2: 125mW,±5%; OUMECLASSIFICATION: 表面実装用固定抵抗器; OUMEMAKERKATAMEI: RN73H1JTTD1001B10; INSTANCENAME: INS9026
R69 = R: PARTNAME: Chip1608_GS_1; ORIGINALSYMBOLORIGIN: (0,0); TIME: 16:40:04; UPDATEUSER: t5459927; SAVECOUNT: 1; QUADMODEL: RES_0; FUNCTION: R_R.Normal_package; CDMASTERCADCELG: KCK0203; MAKER: KOA; RESISTANCETOLER: X; SIZECODESMD: 1608; OUMEMAKER: KOA コーア; ADSCNVFLAG: ON; POWERRATING: 100m; MOUNTINGFORMSMD: SMD; ADSCOMPONENTNAME: R_1608; COMP: PRT_8; ADSMODELNAME: s_RK73Z1JTTD; PMPRODUCTSTYPEG: DME-HD1-PC1; FNLEADFREETHET1GT2GMCTH1: 3_2_N; VAL3: RK73Z1JTTD; VAL2: 100mW; OUMECLASSIFICATION: 表面実装用固定抵抗器; INSTANCENAME: INS8986
R70 = R: PARTNAME: Chip1608_GS_1; ORIGINALSYMBOLORIGIN: (0,0); TIME: 16:40:04; UPDATEUSER: t5459927; SAVECOUNT: 1; QUADMODEL: RES_0; FUNCTION: R_R.Normal_package; CDMASTERCADCELG: KCK0203; MAKER: KOA; RESISTANCETOLER: X; SIZECODESMD: 1608; OUMEMAKER: KOA コーア; POWERRATING: 100m; MOUNTINGFORMSMD: SMD; COMP: PRT_8; ADSMODELNAME: s_RK73Z1JTTD; PMPRODUCTSTYPEG: DME-HD1-PC1; FNLEADFREETHET1GT2GMCTH1: 3_2_N; VAL3: RK73Z1JTTD; VAL2: 100mW; OUMECLASSIFICATION: 表面実装用固定抵抗器; INSTANCENAME: INS8932
R75 = R: PARTNAME: Chip1608_GS_1; ORIGINALSYMBOLORIGIN: (0,0); TIME: 16:40:04; UPDATEUSER: t5459927; SAVECOUNT: 1; QUADMODEL: RES_49.9; FUNCTION: R_R.Normal_package; MAKER: KOA; RESISTANCETOLER: D; SIZECODESMD: 1608; OUMEMAKER: KOA コーア; POWERRATING: 100m; MOUNTINGFORMSMD: SMD; COMP: PRT_8; ADSMODELNAME: s_RK73H1JTTD49R9D@@; FNLEADFREETHET1GT2GMCTH1: N_N_N; VAL3: RK73H1JTTD49R9F; VAL2: 125mW,±1%; OUMECLASSIFICATION: 表面実装用固定抵抗器; OUMEMAKERKATAMEI: RK73H1JTTD49R9D@@; INSTANCENAME: INS8944
R180 = R: PARTNAME: Chip1608_GS_1; ORIGINALSYMBOLORIGIN: (0,0); TIME: 16:40:04; UPDATEUSER: t5459927; SAVECOUNT: 1; QUADMODEL: RES_0; FUNCTION: R_R.Normal_package; CDMASTERCADCELG: KCK0203; MAKER: KOA; RESISTANCETOLER: X; SIZECODESMD: 1608; OUMEMAKER: KOA コーア; POWERRATING: 100m; MOUNTINGFORMSMD: SMD; COMP: PRT_8; ADSMODELNAME: s_RK73Z1JTTD; PMPRODUCTSTYPEG: DME-HD1-PC1; FNLEADFREETHET1GT2GMCTH1: 3_2_N; VAL3: RK73Z1JTTD; VAL2: 100mW; OUMECLASSIFICATION: 表面実装用固定抵抗器; INSTANCENAME: INS8802
R181 = R: PARTNAME: Chip1608_GS_1; ORIGINALSYMBOLORIGIN: (0,0); TIME: 16:40:04; UPDATEUSER: t5459927; SAVECOUNT: 1; QUADMODEL: RES_0; FUNCTION: R_R.Normal_package; CDMASTERCADCELG: KCK0203; MAKER: KOA; RESISTANCETOLER: X; SIZECODESMD: 1608; OUMEMAKER: KOA コーア; POWERRATING: 100m; MOUNTINGFORMSMD: SMD; COMP: PRT_8; ADSMODELNAME: s_RK73Z1JTTD; PMPRODUCTSTYPEG: DME-HD1-PC1; FNLEADFREETHET1GT2GMCTH1: 3_2_N; VAL3: RK73Z1JTTD; VAL2: 100mW; OUMECLASSIFICATION: 表面実装用固定抵抗器; INSTANCENAME: INS8814
R182 = R: PARTNAME: Chip1608_GS_1; ORIGINALSYMBOLORIGIN: (0,0); TIME: 16:40:04; UPDATEUSER: t5459927; SAVECOUNT: 1; QUADMODEL: RES_0; FUNCTION: R_R.Normal_package; CDMASTERCADCELG: KCK0203; MAKER: KOA; RESISTANCETOLER: X; SIZECODESMD: 1608; OUMEMAKER: KOA コーア; POWERRATING: 100m; MOUNTINGFORMSMD: SMD; COMP: PRT_8; ADSMODELNAME: s_RK73Z1JTTD; PMPRODUCTSTYPEG: DME-HD1-PC1; FNLEADFREETHET1GT2GMCTH1: 3_2_N; VAL3: RK73Z1JTTD; VAL2: 100mW; OUMECLASSIFICATION: 表面実装用固定抵抗器; INSTANCENAME: INS8826
R184 = R: PARTNAME: Chip1608_GS_1; ORIGINALSYMBOLORIGIN: (0,0); TIME: 16:40:04; UPDATEUSER: t5459927; SAVECOUNT: 1; QUADMODEL: RES_0; FUNCTION: R_R.Normal_package; CDMASTERCADCELG: KCK0203; MAKER: KOA; RESISTANCETOLER: X; SIZECODESMD: 1608; OUMEMAKER: KOA コーア; POWERRATING: 100m; MOUNTINGFORMSMD: SMD; COMP: PRT_8; ADSMODELNAME: s_RK73Z1JTTD; PMPRODUCTSTYPEG: DME-HD1-PC1; FNLEADFREETHET1GT2GMCTH1: 3_2_N; VAL3: RK73Z1JTTD; VAL2: 100mW; OUMECLASSIFICATION: 表面実装用固定抵抗器; INSTANCENAME: INS9056
R185 = R: PARTNAME: Chip3216_GS_1; ORIGINALSYMBOLORIGIN: (0,0); TIME: 16:40:04; UPDATEUSER: t5459927; SAVECOUNT: 1; QUADMODEL: RES_22; FUNCTION: R_R.Normal_package; CDMASTERCADCELG: DR901A; MAKER: PANASONIC; RESISTANCETOLER: J; SIZECODESMD: 3216; OUMEMAKER: ROH ロー・; POWERRATING: 250m; MOUNTINGFORMSMD: SMD; NOMINALRESISTAN: 22; COMP: PRT_5; ADSMODELNAME: s_MCR18EZHJ220; FNLEADFREETHET1GT2GMCTH1: N_N_N; VAL3: ERJ-8GEYJ200V; VAL2: 250mW,±5%; OUMECLASSIFICATION: 表面実装用固定抵抗器; OUMEMAKERKATAMEI: MCR18EZHJ220; INSTANCENAME: INS9068
R207 = R: PARTNAME: Chip1608_GS_1; ORIGINALSYMBOLORIGIN: (0,0); TIME: 16:40:04; UPDATEUSER: t5459927; SAVECOUNT: 1; QUADMODEL: RES_0; FUNCTION: R_R.Normal_package; CDMASTERCADCELG: KCK0203; MAKER: KOA; RESISTANCETOLER: X; SIZECODESMD: 1608; OUMEMAKER: KOA コーア; POWERRATING: 100m; MOUNTINGFORMSMD: SMD; COMP: PRT_8; ADSMODELNAME: s_RK73Z1JTTD; PMPRODUCTSTYPEG: DME-HD1-PC1; FNLEADFREETHET1GT2GMCTH1: 3_2_N; VAL3: RK73Z1JTTD; VAL2: 100mW; OUMECLASSIFICATION: 表面実装用固定抵抗器; INSTANCENAME: INS9110
R208 = R: PARTNAME: Chip1608_GS_1; ORIGINALSYMBOLORIGIN: (0,0); TIME: 16:40:04; UPDATEUSER: t5459927; SAVECOUNT: 1; QUADMODEL: RES_0; FUNCTION: R_R.Normal_package; CDMASTERCADCELG: KCK0203; MAKER: KOA; RESISTANCETOLER: X; SIZECODESMD: 1608; OUMEMAKER: KOA コーア; POWERRATING: 100m; MOUNTINGFORMSMD: SMD; COMP: PRT_8; ADSMODELNAME: s_RK73Z1JTTD; PMPRODUCTSTYPEG: DME-HD1-PC1; FNLEADFREETHET1GT2GMCTH1: 3_2_N; VAL3: RK73Z1JTTD; VAL2: 100mW; OUMECLASSIFICATION: 表面実装用固定抵抗器; INSTANCENAME: INS8920
R209 = R: PARTNAME: Chip1608_GS_1; ORIGINALSYMBOLORIGIN: (0,0); TIME: 16:40:04; UPDATEUSER: t5459927; SAVECOUNT: 1; QUADMODEL: RES_0; FUNCTION: R_R.Normal_package; CDMASTERCADCELG: KCK0203; MAKER: KOA; RESISTANCETOLER: X; SIZECODESMD: 1608; OUMEMAKER: KOA コーア; POWERRATING: 100m; MOUNTINGFORMSMD: SMD; COMP: PRT_8; ADSMODELNAME: s_RK73Z1JTTD; PMPRODUCTSTYPEG: DME-HD1-PC1; FNLEADFREETHET1GT2GMCTH1: 3_2_N; VAL3: RK73Z1JTTD; VAL2: 100mW; OUMECLASSIFICATION: 表面実装用固定抵抗器; INSTANCENAME: INS8908
R210 = R: PARTNAME: Chip1608_GS_1; ORIGINALSYMBOLORIGIN: (0,0); TIME: 16:40:04; UPDATEUSER: t5459927; SAVECOUNT: 1; COMPONENTNAME: R_R.Normal_package; ADSMODELNAME: s_ERJ2RHD163X; VAL3: RK73B1JTTD682J; MOUNTINGFORMSMD: SMD; VAL2: 100mW,±5%; PMPRODUCTSTYPEG: DME-HD1; COMP: PRT_8; ADSCOMPONENTNAME: R_1005; CHIPSIZE: 1608; INSTANCENAME: INS8738
R211 = R: PARTNAME: Chip1608_GS_1; ORIGINALSYMBOLORIGIN: (0,0); TIME: 16:40:04; UPDATEUSER: t5459927; SAVECOUNT: 1; COMPONENTNAME: R_R.Normal_package; ADSMODELNAME: s_ERJ2RHD163X; VAL3: RK73B1JTTD682J; MOUNTINGFORMSMD: SMD; MAKER: KOA; VAL2: 100mW,±5%; PMPRODUCTSTYPEG: DME-HD1; COMP: PRT_8; ADSCOMPONENTNAME: R_1005; CHIPSIZE: 1608; INSTANCENAME: INS8750
TP42 = TP: PARTNAME: LC-22_GS; UPDATEUSER: t5459927; UPDATETIME: 16:40:05; SAVECOUNT: 1; SAVEAREA0: -242,-92,12810,7836; ORIGINALSYMBOLORIGIN: (0,0); COMPONENTNAME: TP_TP.Normal_package; ID: LGND; MAKER: MAC8; COMP: PRT_34; INSTANCENAME: INS9148
U?#6 = WAKU_DEF100: PLOTTIME: HH:MM; SAVEAREA0: 168739,-66042,466246,90057; TIME: 14:30:25; UPDATEUSER: t5459927; UPDATETIME: 15:16:58; SAVECOUNT: 5; OriginalSymbolOrigin: (10160,284480)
